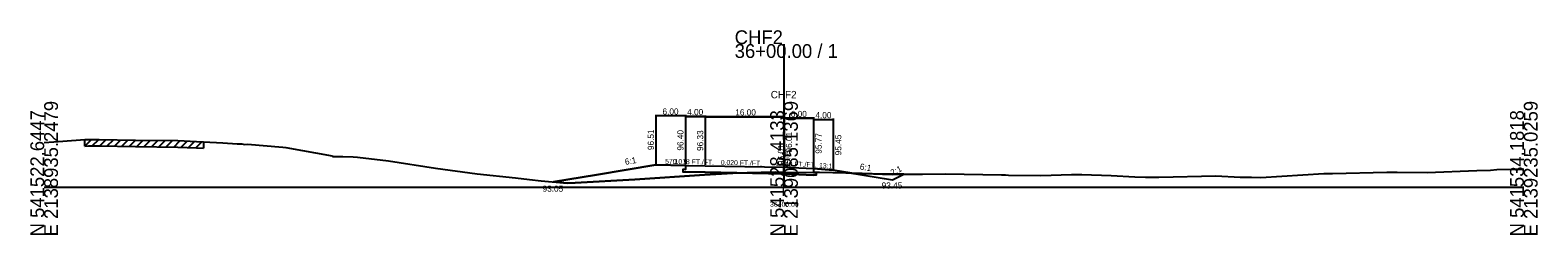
# Model space of a CAD drawing. Extents: x -12831 to 2303, y -10 to 39065.
# Drawn here: x 997.2 to 1302.8, y 11990.3 to 12031.8 of the extents above; entities that cross this region are included whole.
import ezdxf

# ---------------------------------------------------------------- set-up
doc = ezdxf.new("R2010")
doc.units = 0
for name, color, linetype in [('Level 5', 7, 'Continuous'), ('Level 53', 7, 'Continuous'), ('Level 54', 7, 'Continuous'), ('Level 55', 7, 'Continuous'), ('Level 7', 7, 'Continuous'), ('RD_GPK_XS_Cell', 7, 'Continuous'), ('RD_XS_EwShp', 7, 'Continuous'), ('RD_XS_ExGround', 7, 'Continuous'), ('RD_XS_ExPaveRet', 7, 'Continuous'), ('RD_XS_Pave', 7, 'Continuous'), ('RD_XS_TX_Baseline', 7, 'Continuous'), ('RD_XS_TX_Elev_EX', 7, 'Continuous'), ('RD_XS_TX_Elev_PR', 7, 'Continuous'), ('RD_XS_TX_Station', 7, 'Continuous')]:
    doc.layers.add(name, color=color, linetype=linetype)

msp = doc.modelspace()

# ---------------------------------------------------------------- linework, layer by layer
at = {"layer": 'Level 5'}
for p, q in [((1130, 12004.4), (1130, 12003.57)), ((1129.5, 12003.58), (1129.5, 12003.08)), ((1130, 12003.57), (1129.5, 12003.58)), ((1129.5, 12003.08), (1130, 12003.07)), ((1134, 12003), (1130, 12003.07)), ((1134, 12003), (1130, 12003.07)), ((1130, 12003.07), (1134, 12003)), ((1150, 12002.68), (1134, 12003)), ((1150, 12002.68), (1134, 12003)), ((1134, 12003), (1150, 12002.68)), ((1134, 12003), (1150, 12002.68)), ((1156, 12002.44), (1150, 12002.68)), ((1150, 12002.68), (1156, 12002.44)), ((1150, 12002.68), (1156, 12002.44)), ((1156, 12003.77), (1156, 12002.94)), ((1156, 12002.94), (1156.5, 12002.92)), ((1156.5, 12002.42), (1156, 12002.44)), ((1156.5, 12002.92), (1156.5, 12002.42))]:
    msp.add_line(p, q, dxfattribs=at)
at = {"layer": 'Level 54'}
for p, q in [((1124, 12014.66), (1124, 12004.71)), ((1130, 12014.46), (1124, 12014.46)), ((1130, 12014.66), (1130, 12004.6)), ((1130, 12014.55), (1130, 12004.6)), ((1130, 12014.55), (1130, 12004.6)), ((1130, 12014.55), (1130, 12004.6)), ((1130, 12014.35), (1134, 12014.35)), ((1130, 12014.35), (1134, 12014.35)), ((1134, 12014.35), (1130, 12014.35)), ((1134, 12014.55), (1134, 12004.53)), ((1134, 12014.55), (1134, 12004.53)), ((1134, 12014.55), (1134, 12004.53)), ((1134, 12014.48), (1134, 12004.53)), ((1134, 12014.48), (1134, 12004.53)), ((1134, 12014.48), (1134, 12004.53)), ((1134, 12014.48), (1134, 12004.53)), ((1134, 12014.28), (1150, 12014.28)), ((1134, 12014.28), (1150, 12014.28)), ((1150, 12014.28), (1134, 12014.28)), ((1150, 12014.28), (1134, 12014.28)), ((1150, 12014.48), (1150, 12004.21)), ((1150, 12014.48), (1150, 12004.21)), ((1150, 12014.48), (1150, 12004.21)), ((1150, 12014.48), (1150, 12004.21)), ((1150, 12014.16), (1150, 12004.21)), ((1150, 12014.16), (1150, 12004.21)), ((1150, 12014.16), (1150, 12004.21)), ((1150, 12013.96), (1156, 12013.96)), ((1156, 12013.96), (1150, 12013.96)), ((1156, 12013.96), (1150, 12013.96)), ((1156, 12014.16), (1156, 12003.97)), ((1156, 12014.16), (1156, 12003.97)), ((1156, 12014.16), (1156, 12003.97)), ((1156, 12013.92), (1156, 12003.97)), ((1156, 12013.72), (1160, 12013.72)), ((1160, 12013.92), (1160, 12003.65))]:
    msp.add_line(p, q, dxfattribs=at)
at = {"layer": 'Level 7'}
for p, q in [((1124, 12004.51), (1112, 12002.51)), ((1130, 12004.4), (1124, 12004.51)), ((1112, 12002.51), (1103.27, 12001.05)), ((1156, 12003.77), (1160, 12003.45)), ((1160, 12003.45), (1172, 12001.45)), ((1172, 12001.45), (1174.28, 12002.59))]:
    msp.add_line(p, q, dxfattribs=at)
at = {"layer": 'RD_GPK_XS_Cell'}
for p, q in [((1150, 12000), (1150, 12029)), ((1000, 12000), (1150, 12000)), ((1150, 12000), (1300, 12000))]:
    msp.add_line(p, q, dxfattribs=at)
at = {"layer": 'RD_XS_EwShp'}
for points in [[(1130, 12004.4), (1130, 12003.57), (1129.5, 12003.58), (1129.5, 12003.08), (1130, 12003.07), (1134, 12003), (1140.36, 12002.87), (1139.6, 12002.83), (1133.88, 12002.48), (1119.75, 12001.52), (1107.65, 12000.85), (1106.04, 12000.8), (1103.27, 12001.05), (1112, 12002.51), (1124, 12004.51)], [(1150, 12002.68), (1140.36, 12002.87), (1140.89, 12002.9), (1142.56, 12002.96), (1148.18, 12003.11), (1149.56, 12003.06), (1150, 12003.05), (1152.38, 12002.99), (1156, 12003.03), (1156, 12002.94), (1156.5, 12002.92), (1156.5, 12002.42), (1156, 12002.44)], [(1156, 12003.03), (1157.18, 12003.04), (1162.53, 12002.87), (1163.78, 12002.82), (1160, 12003.45), (1156, 12003.77)], [(1172, 12001.45), (1174.28, 12002.59), (1169.97, 12002.6), (1163.78, 12002.82)]]:
    msp.add_lwpolyline(points, close=True, dxfattribs=at)
at = {"layer": 'RD_XS_ExGround'}
for p, q in [((1000, 12009.06), (1001.96, 12009.19)), ((1001.96, 12009.19), (1007.35, 12009.59)), ((1007.35, 12009.59), (1008.25, 12009.63)), ((1008.25, 12009.63), (1009.02, 12009.64)), ((1009.02, 12009.64), (1011.15, 12009.67)), ((1011.15, 12009.67), (1018.5, 12009.54)), ((1018.5, 12009.54), (1027.13, 12009.42)), ((1027.13, 12009.42), (1030.86, 12009.27)), ((1030.86, 12009.27), (1032.32, 12009.21)), ((1032.32, 12009.21), (1036.23, 12008.97)), ((1036.23, 12008.97), (1039.13, 12008.78)), ((1039.13, 12008.78), (1040.06, 12008.76)), ((1040.06, 12008.76), (1040.62, 12008.66)), ((1040.62, 12008.66), (1041.22, 12008.73)), ((1041.22, 12008.73), (1048.38, 12008.1)), ((1048.38, 12008.1), (1048.99, 12008.04)), ((1048.99, 12008.04), (1058.38, 12006.33)), ((1058.38, 12006.33), (1058.47, 12006.19)), ((1058.47, 12006.19), (1060.55, 12006.18)), ((1060.55, 12006.18), (1062.66, 12006.17)), ((1062.66, 12006.17), (1063.53, 12006.07)), ((1063.53, 12006.07), (1069.82, 12005.31)), ((1069.82, 12005.31), (1079.37, 12003.86)), ((1079.37, 12003.86), (1087.82, 12002.68)), ((1087.82, 12002.68), (1095.54, 12001.85)), ((1095.54, 12001.85), (1098.42, 12001.52)), ((1098.42, 12001.52), (1100.77, 12001.28)), ((1100.77, 12001.28), (1106.04, 12000.8)), ((1107.65, 12000.85), (1119.75, 12001.52)), ((1119.75, 12001.52), (1133.88, 12002.48)), ((1133.88, 12002.48), (1139.6, 12002.83)), ((1139.6, 12002.83), (1140.89, 12002.9)), ((1140.89, 12002.9), (1142.56, 12002.96)), ((1142.56, 12002.96), (1148.18, 12003.11)), ((1148.18, 12003.11), (1149.56, 12003.06)), ((1149.56, 12003.06), (1150, 12003.05)), ((1150, 12003.05), (1152.38, 12002.99)), ((1152.38, 12002.99), (1157.18, 12003.04)), ((1157.18, 12003.04), (1162.53, 12002.87)), ((1162.53, 12002.87), (1169.97, 12002.6)), ((1169.97, 12002.6), (1178.1, 12002.59)), ((1178.1, 12002.59), (1182.75, 12002.66)), ((1182.75, 12002.66), (1194.08, 12002.47)), ((1194.08, 12002.47), (1194.89, 12002.46)), ((1194.89, 12002.46), (1195.53, 12002.43)), ((1195.53, 12002.43), (1202.08, 12002.38)), ((1202.08, 12002.38), (1208.32, 12002.53)), ((1208.32, 12002.53), (1209.23, 12002.54)), ((1209.23, 12002.54), (1210.39, 12002.52)), ((1210.39, 12002.52), (1216.34, 12002.33)), ((1216.34, 12002.33), (1221.1, 12002.1)), ((1221.1, 12002.1), (1223.31, 12001.98)), ((1223.31, 12001.98), (1225.99, 12002.04)), ((1225.99, 12002.04), (1237.57, 12002.28)), ((1237.57, 12002.28), (1242.46, 12002.04)), ((1242.46, 12002.04), (1244.75, 12001.98)), ((1244.75, 12001.98), (1246.67, 12001.95)), ((1246.67, 12001.95), (1259.45, 12002.75)), ((1259.45, 12002.75), (1261.24, 12002.79)), ((1261.24, 12002.79), (1272.23, 12003.02)), ((1272.23, 12003.02), (1273.12, 12003.04)), ((1273.12, 12003.04), (1274.29, 12003.04)), ((1274.29, 12003.04), (1280.38, 12002.96)), ((1280.38, 12002.96), (1290.46, 12003.36)), ((1290.46, 12003.36), (1293.24, 12003.46)), ((1293.24, 12003.46), (1294.55, 12003.56)), ((1294.55, 12003.56), (1297.8, 12003.63)), ((1297.8, 12003.63), (1300, 12003.64)), ((1106.04, 12000.8), (1107.65, 12000.85))]:
    msp.add_line(p, q, dxfattribs=at)
at = {"layer": 'RD_XS_ExPaveRet'}
for p, q in [((1008.25, 12008.33), (1009.57, 12009.65)), ((1008.25, 12008.33), (1008.25, 12009.63)), ((1008.25, 12008.33), (1009.02, 12008.34)), ((1009.02, 12008.34), (1011.15, 12008.37)), ((1009.76, 12008.35), (1011.07, 12009.67)), ((1011.15, 12008.37), (1018.5, 12008.24)), ((1011.26, 12008.36), (1012.54, 12009.64)), ((1012.76, 12008.34), (1014.04, 12009.62)), ((1014.26, 12008.31), (1015.54, 12009.59)), ((1015.76, 12008.29), (1017.04, 12009.57)), ((1017.26, 12008.26), (1018.54, 12009.54)), ((1018.5, 12008.24), (1027.13, 12008.12)), ((1018.76, 12008.24), (1020.04, 12009.52)), ((1020.26, 12008.22), (1021.54, 12009.5)), ((1021.76, 12008.2), (1023.04, 12009.48)), ((1023.26, 12008.17), (1024.54, 12009.45)), ((1024.76, 12008.15), (1026.04, 12009.43)), ((1026.26, 12008.13), (1027.53, 12009.4)), ((1027.13, 12008.12), (1030.86, 12007.97)), ((1027.76, 12008.09), (1029.01, 12009.34)), ((1029.26, 12008.03), (1030.51, 12009.28)), ((1030.76, 12007.97), (1032.01, 12009.22)), ((1030.86, 12007.97), (1032.32, 12007.91)), ((1032.32, 12009.21), (1032.32, 12007.91))]:
    msp.add_line(p, q, dxfattribs=at)
at = {"layer": 'RD_XS_Pave'}
for p, q in [((1130, 12004.4), (1134, 12004.33)), ((1134, 12004.33), (1150, 12004.01)), ((1150, 12004.01), (1156, 12003.77))]:
    msp.add_line(p, q, dxfattribs=at)

# ---------------------------------------------------------------- texts
at = {"layer": 'Level 53'}
for s, rotation, p in [('96.51', 90, (1123.62, 12007.51)), ('96.40', 90, (1129.62, 12007.4)), ('96.33', 90, (1133.62, 12007.33)), ('96.33', 90, (1133.62, 12007.33)), ('96.01', 90, (1151.63, 12007.01)), ('96.01', 90, (1151.63, 12007.01)), ('95.77', 90, (1157.63, 12006.77)), ('95.45', 90, (1161.63, 12006.45)), ('6:1', 9.4623, (1117.84, 12004.5)), ('6:1', 350.5377, (1165.3, 12003.59))]:
    msp.add_text(s, height=1.25, rotation=rotation, dxfattribs=at).set_placement(p)
for s, p in [('93.05', (1101.05, 11999.05)), ('93.45', (1169.8, 11999.7))]:
    msp.add_text(s, height=1.25, dxfattribs=at).set_placement(p)
at = {"layer": 'Level 54'}
for s, p in [('6.00', (1125.37, 12014.71)), ('4.00', (1130.37, 12014.6)), ('4.00', (1130.37, 12014.6)), ('4.00', (1130.37, 12014.6)), ('16.00', (1140.12, 12014.53)), ('16.00', (1140.12, 12014.53)), ('16.00', (1140.12, 12014.53)), ('16.00', (1140.12, 12014.53)), ('6.00', (1151.37, 12014.21)), ('6.00', (1151.37, 12014.21)), ('6.00', (1151.37, 12014.21)), ('4.00', (1156.37, 12013.97))]:
    msp.add_text(s, height=1.25, dxfattribs=at).set_placement(p)
at = {"layer": 'Level 55'}
for s, height, rotation, p in [('57:1', 1, 358.9949, (1125.89, 12004.73)), ('0.018 FT./FT.', 1, 358.9949, (1127.43, 12004.7)), ('0.018 FT./FT.', 1, 358.9949, (1127.43, 12004.7)), ('0.018 FT./FT.', 1, 358.9949, (1127.43, 12004.7)), ('0.020 FT./FT.', 1, 358.8542, (1137.18, 12004.52)), ('0.020 FT./FT.', 1, 358.8542, (1137.18, 12004.52)), ('0.020 FT./FT.', 1, 358.8542, (1137.18, 12004.52)), ('0.020 FT./FT.', 1, 358.8542, (1137.18, 12004.52)), ('0.040 FT./FT.', 1, 357.7094, (1148.24, 12004.33)), ('0.040 FT./FT.', 1, 357.7094, (1148.24, 12004.33)), ('0.040 FT./FT.', 1, 357.7094, (1148.24, 12004.33)), ('13:1', 1, 355.4261, (1157.07, 12003.94)), ('2:1', 1.25, 26.5651, (1171.96, 12002.27))]:
    msp.add_text(s, height=height, rotation=rotation, dxfattribs=at).set_placement(p)
at = {"layer": 'RD_GPK_XS_Cell'}
for s, p in [('CHF2', (1140, 12029)), ('36+00.00 / 1', (1140, 12026.2))]:
    msp.add_text(s, height=2.8, dxfattribs=at).set_placement(p)
for s, p in [('E 2138935.2479', (1002.8, 11990)), ('E 2139085.1369', (1152.8, 11990)), ('E 2139235.0259', (1302.8, 11990)), ('N 541522.6447', (1000, 11990)), ('N 541528.4133', (1150, 11990)), ('N 541534.1818', (1300, 11990))]:
    msp.add_text(s, height=2.8, rotation=90, dxfattribs=at).set_placement(p)
at = {"layer": 'RD_XS_TX_Baseline'}
msp.add_text('CHF2', height=1.5, dxfattribs=at).set_placement((1147.31, 12018.01))
at = {"layer": 'RD_XS_TX_Elev_EX'}
msp.add_text('95.05', height=1, rotation=90, dxfattribs=at).set_placement((1151.25, 12004.05))
at = {"layer": 'RD_XS_TX_Elev_PR'}
msp.add_text(' 96.01', height=1.25, rotation=90, dxfattribs=at).set_placement((1150, 12004.01))
at = {"layer": 'RD_XS_TX_Station'}
msp.add_text('36+00.00', height=1, dxfattribs=at).set_placement((1147.17, 11996.01))

doc.saveas('drawing.dxf')
